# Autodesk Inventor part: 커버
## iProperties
Company: 한국ATC센터
Created: 2014-12
Part Number: 커버
Document SubType Name: Modeling
Designer: KYOUNG IL JANG
Density: 1 g/cm^3
Mass: 160.364 g
Surface Area: 512.085 cm^2
Volume: 160.364 cm^3
Author: KYOUNG IL JANG
